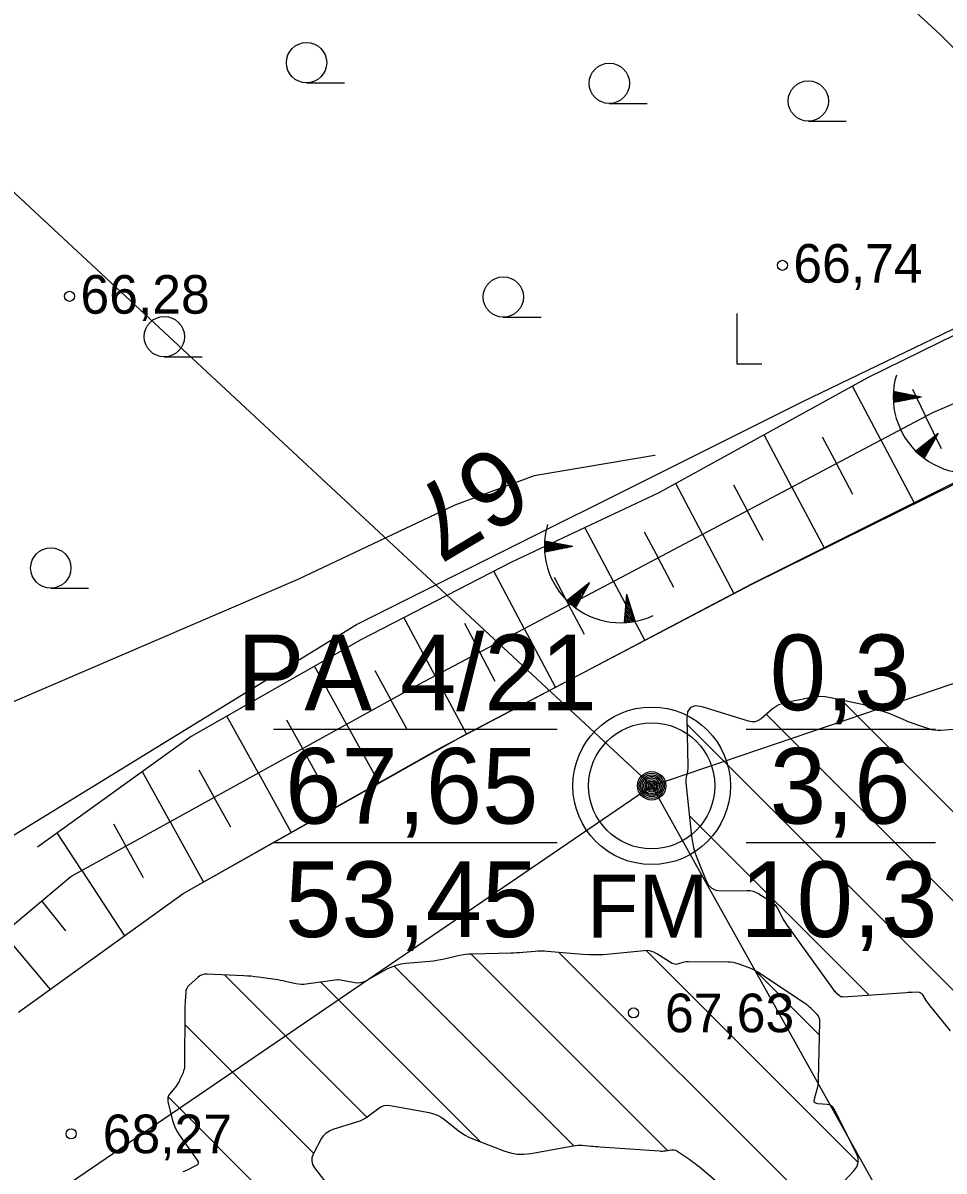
# Model space of a CAD drawing. Extents: x 532503 to 539665, y 6557663 to 6561526.
# Drawn here: x 535265.8 to 535324.2, y 6559863.4 to 6559936.3 of the extents above; entities that cross this region are included whole.
import ezdxf

# ---------------------------------------------------------------- set-up
doc = ezdxf.new("R2010")
doc.units = 0
for name, color, linetype in [('Default', 7, 'Continuous'), ('GEOLPUNKT', 7, 'Continuous'), ('HALJASTUS', 7, 'Continuous'), ('HORISONTAAL-EH2000', 7, 'Continuous'), ('Kaevandatud ala', 7, 'Continuous'), ('KORGUS-EH2000', 7, 'Continuous'), ('Lamami horisontaal_EH2000', 7, 'Continuous'), ('Lõige', 7, 'Continuous'), ('Proovid', 7, 'Continuous'), ('RELJEEF', 7, 'Continuous')]:
    doc.layers.add(name, color=color, linetype=linetype)

# ---------------------------------------------------------------- blocks, each defined once
blk = doc.blocks.new('RAIESM')
at = {"layer": 'Default'}
for points in [[(0, 2), (0, 0)], [(0, 0), (1, 0)]]:
    blk.add_lwpolyline(points, dxfattribs=at)
blk = doc.blocks.new('HARVIK')
at = {"layer": 'HALJASTUS'}
blk.add_line((0, -0.8), (1.5, -0.8), dxfattribs=at)
blk.add_circle((0, 0), 0.8, dxfattribs=at)

msp = doc.modelspace()

# ---------------------------------------------------------------- linework, layer by layer
at = {"layer": 'GEOLPUNKT'}
for p, q in [((535281.655, 6559891.451), (535299.655, 6559891.451)), ((535311.655, 6559891.451), (535323.655, 6559891.451)), ((535281.655, 6559884.251), (535299.655, 6559884.251)), ((535311.655, 6559884.251), (535323.655, 6559884.251))]:
    msp.add_line(p, q, dxfattribs=at)
for radius in [5, 4, 0.9, 0.801, 0.7, 0.6, 0.5, 0.4, 0.3, 0.2, 0.1]:
    msp.add_circle((535305.655, 6559887.851), radius, dxfattribs=at)
at = {"layer": 'HORISONTAAL-EH2000'}
msp.add_lwpolyline([(535305.885, 6559908.809), (535305.842, 6559908.814), (535298.198, 6559907.517), (535293.16, 6559905.657), (535283.197, 6559900.951), (535256.192, 6559889.327), (535239.185, 6559882.188), (535229.031, 6559879.316), (535223.831, 6559878.54), (535205.549, 6559877.823), (535200.022, 6559876.846), (535189.2, 6559873.548), (535161, 6559862.943), (535143.069, 6559857.274), (535133.961, 6559854.956), (535125.581, 6559853.165), (535108.623, 6559850.369), (535095.453, 6559849.117), (535088.898, 6559849.291), (535083.275, 6559850.063), (535072.085, 6559852.426), (535042.226, 6559857.773)], dxfattribs=at)
at = {"layer": 'Kaevandatud ala'}
for p, q in [((535317.672, 6559893.299), (535344.443, 6559866.528)), ((535312.923, 6559892.392), (535341.11, 6559864.204)), ((535307.887, 6559891.77), (535333.788, 6559865.87)), ((535308.045, 6559885.956), (535319.423, 6559874.578)), ((535294.203, 6559877.17), (535306.663, 6559864.711)), ((535299.755, 6559877.275), (535315.17, 6559861.861)), ((535305.297, 6559877.39), (535318.754, 6559863.933)), ((535289.313, 6559876.404), (535300.702, 6559865.014)), ((535312.237, 6559876.107), (535316.31, 6559872.034)), ((535278.552, 6559875.851), (535287.579, 6559866.824)), ((535284.667, 6559875.393), (535294.816, 6559865.244)), ((535276.035, 6559872.711), (535284.227, 6559864.519)), ((535274.978, 6559868.111), (535299.734, 6559843.355))]:
    msp.add_line(p, q, dxfattribs=at)
for points in [[(535325.558, 6559891.481), (535323.992, 6559891.37), (535323.797, 6559891.366), (535323.605, 6559891.38), (535323.415, 6559891.414), (535323.228, 6559891.466), (535322.483, 6559891.714), (535322.297, 6559891.778), (535322.113, 6559891.846), (535321.931, 6559891.918), (535321.75, 6559891.994), (535321.015, 6559892.312), (535320.832, 6559892.389), (535320.648, 6559892.462), (535320.462, 6559892.532), (535320.274, 6559892.598), (535319.495, 6559892.865), (535319.301, 6559892.928), (535319.106, 6559892.985), (535318.91, 6559893.036), (535318.711, 6559893.081), (535316.993, 6559893.442), (535316.659, 6559893.494), (535316.326, 6559893.511), (535315.992, 6559893.494), (535315.659, 6559893.44), (535314.113, 6559893.113), (535313.891, 6559893.052), (535313.682, 6559892.965), (535313.486, 6559892.853), (535313.302, 6559892.715), (535312.593, 6559892.112), (535312.41, 6559891.989), (535312.216, 6559891.92), (535312.01, 6559891.907), (535311.793, 6559891.948), (535308.867, 6559892.857), (535308.425, 6559892.928), (535308.113, 6559892.828), (535307.931, 6559892.555), (535307.879, 6559892.11), (535307.953, 6559889.102), (535307.953, 6559889.013), (535307.947, 6559888.926), (535307.935, 6559888.839), (535307.918, 6559888.752), (535307.838, 6559888.407), (535307.822, 6559888.321), (535307.813, 6559888.234), (535307.812, 6559888.146), (535307.818, 6559888.058), (535308.187, 6559884.647), (535308.238, 6559884.285), (535308.314, 6559883.928), (535308.415, 6559883.577), (535308.54, 6559883.233), (535309.106, 6559881.821), (535309.26, 6559881.543), (535309.469, 6559881.345), (535309.731, 6559881.228), (535310.048, 6559881.191), (535311.69, 6559881.209), (535311.894, 6559881.197), (535312.09, 6559881.156), (535312.278, 6559881.087), (535312.458, 6559880.989), (535313.257, 6559880.478), (535313.377, 6559880.389), (535313.483, 6559880.288), (535313.575, 6559880.174), (535313.651, 6559880.046), (535313.93, 6559879.509), (535314.002, 6559879.376), (535314.079, 6559879.246), (535314.16, 6559879.118), (535314.246, 6559878.994), (535317.121, 6559874.979), (535317.166, 6559874.92), (535317.214, 6559874.863), (535317.265, 6559874.809), (535317.319, 6559874.758), (535317.541, 6559874.558), (535317.599, 6559874.515), (535317.662, 6559874.485), (535317.729, 6559874.47), (535317.801, 6559874.468), (535321.818, 6559874.742), (535321.907, 6559874.747), (535321.997, 6559874.752), (535322.086, 6559874.755), (535322.176, 6559874.758), (535322.533, 6559874.766), (535322.617, 6559874.758), (535322.691, 6559874.731), (535322.754, 6559874.684), (535322.806, 6559874.618), (535323.049, 6559874.226), (535323.106, 6559874.136), (535323.167, 6559874.048), (535323.23, 6559873.962), (535323.296, 6559873.879), (535324.585, 6559872.29)], [(535317.557, 6559862.427), (535318.486, 6559863.42), (535318.67, 6559863.675), (535318.758, 6559863.944), (535318.749, 6559864.227), (535318.644, 6559864.524), (535317.226, 6559867.336), (535317.148, 6559867.455), (535317.05, 6559867.543), (535316.931, 6559867.6), (535316.791, 6559867.627), (535316.192, 6559867.672), (535316.066, 6559867.7), (535315.988, 6559867.761), (535315.957, 6559867.856), (535315.974, 6559867.984), (535316.148, 6559868.599), (535316.186, 6559868.751), (535316.214, 6559868.904), (535316.232, 6559869.058), (535316.241, 6559869.214), (535316.331, 6559872.879), (535316.322, 6559873.008), (535316.288, 6559873.127), (535316.231, 6559873.236), (535316.148, 6559873.336), (535315.77, 6559873.714), (535315.673, 6559873.806), (535315.572, 6559873.893), (535315.467, 6559873.975), (535315.358, 6559874.051), (535312.389, 6559876.014), (535312.245, 6559876.103), (535312.097, 6559876.183), (535311.944, 6559876.253), (535311.786, 6559876.315), (535311.146, 6559876.542), (535310.985, 6559876.592), (535310.821, 6559876.628), (535310.655, 6559876.651), (535310.486, 6559876.659), (535307.994, 6559876.688), (535307.903, 6559876.685), (535307.813, 6559876.676), (535307.725, 6559876.661), (535307.637, 6559876.639), (535307.287, 6559876.537), (535307.2, 6559876.52), (535307.117, 6559876.523), (535307.036, 6559876.544), (535306.957, 6559876.583), (535305.989, 6559877.196), (535305.797, 6559877.296), (535305.598, 6559877.362), (535305.39, 6559877.392), (535305.174, 6559877.387), (535303.015, 6559877.164), (535302.582, 6559877.13), (535302.148, 6559877.115), (535301.715, 6559877.121), (535301.281, 6559877.147), (535299.025, 6559877.336), (535298.833, 6559877.348), (535298.641, 6559877.352), (535298.448, 6559877.348), (535298.256, 6559877.336), (535297.487, 6559877.271), (535297.295, 6559877.256), (535297.102, 6559877.244), (535296.909, 6559877.236), (535296.717, 6559877.23), (535294.295, 6559877.175), (535294.065, 6559877.164), (535293.837, 6559877.141), (535293.61, 6559877.107), (535293.385, 6559877.061), (535292.486, 6559876.853), (535292.261, 6559876.805), (535292.035, 6559876.765), (535291.807, 6559876.732), (535291.578, 6559876.708), (535290.054, 6559876.569), (535289.742, 6559876.525), (535289.439, 6559876.45), (535289.146, 6559876.343), (535288.863, 6559876.206), (535287.504, 6559875.461), (535287.345, 6559875.389), (535287.181, 6559875.347), (535287.012, 6559875.334), (535286.838, 6559875.35), (535285.792, 6559875.534), (535285.78, 6559875.536), (535285.768, 6559875.539), (535285.745, 6559875.546), (535285.739, 6559875.547), (535285.733, 6559875.548), (535285.727, 6559875.548), (535285.721, 6559875.547), (535283.746, 6559875.258), (535283.58, 6559875.242), (535283.415, 6559875.241), (535283.251, 6559875.255), (535283.087, 6559875.285), (535282.433, 6559875.437), (535282.269, 6559875.473), (535282.105, 6559875.505), (535281.939, 6559875.534), (535281.773, 6559875.559), (535280.711, 6559875.706), (535280.478, 6559875.735), (535280.245, 6559875.76), (535280.011, 6559875.779), (535279.777, 6559875.793), (535277.457, 6559875.903), (535277.294, 6559875.896), (535277.141, 6559875.859), (535276.998, 6559875.792), (535276.867, 6559875.694), (535276.318, 6559875.205), (535276.226, 6559875.106), (535276.157, 6559874.996), (535276.113, 6559874.873), (535276.092, 6559874.739), (535276.059, 6559874.181), (535276.051, 6559874.041), (535276.046, 6559873.901), (535276.042, 6559873.761), (535276.04, 6559873.621), (535276.019, 6559870.104), (535276.013, 6559869.985), (535275.995, 6559869.869), (535275.964, 6559869.755), (535275.923, 6559869.643), (535275.732, 6559869.201), (535275.681, 6559869.093), (535275.622, 6559868.989), (535275.556, 6559868.89), (535275.484, 6559868.795), (535275.084, 6559868.31), (535275.008, 6559868.194), (535274.964, 6559868.072), (535274.951, 6559867.942), (535274.97, 6559867.805), (535275.266, 6559866.609), (535275.338, 6559866.367), (535275.431, 6559866.136), (535275.545, 6559865.914), (535275.681, 6559865.703), (535276.823, 6559864.093), (535276.882, 6559863.978), (535276.885, 6559863.878), (535276.834, 6559863.792), (535276.726, 6559863.721), (535276.186, 6559863.464), (535276.049, 6559863.403), (535275.911, 6559863.349)], [(535285.137, 6559862.505), (535284.291, 6559863.598), (535284.164, 6559863.811), (535284.109, 6559864.03), (535284.124, 6559864.255), (535284.21, 6559864.486), (535284.697, 6559865.426), (535284.835, 6559865.641), (535285.005, 6559865.818), (535285.209, 6559865.955), (535285.445, 6559866.053), (535286.96, 6559866.523), (535287.153, 6559866.592), (535287.337, 6559866.677), (535287.514, 6559866.778), (535287.682, 6559866.895), (535288.337, 6559867.395), (535288.506, 6559867.499), (535288.684, 6559867.563), (535288.872, 6559867.586), (535289.07, 6559867.569), (535291.546, 6559867.106), (535291.808, 6559867.041)], [(535291.808, 6559867.041), (535292.057, 6559866.945), (535292.292, 6559866.819), (535292.513, 6559866.663), (535293.37, 6559865.978), (535293.589, 6559865.816), (535293.819, 6559865.672), (535294.059, 6559865.546), (535294.31, 6559865.439), (535296.284, 6559864.679), (535296.701, 6559864.55), (535297.123, 6559864.48), (535297.551, 6559864.47), (535297.985, 6559864.52), (535300.679, 6559865.011), (535300.819, 6559865.032), (535300.96, 6559865.043), (535301.101, 6559865.045), (535301.243, 6559865.038), (535301.811, 6559864.99), (535301.953, 6559864.978), (535302.095, 6559864.967), (535302.237, 6559864.956), (535302.379, 6559864.946), (535306.147, 6559864.673), (535306.242, 6559864.669), (535306.337, 6559864.67), (535306.431, 6559864.677), (535306.526, 6559864.689), (535306.903, 6559864.749), (535306.995, 6559864.755), (535307.084, 6559864.745), (535307.169, 6559864.717), (535307.25, 6559864.673), (535308.07, 6559864.128), (535308.232, 6559864.017), (535308.39, 6559863.902), (535308.544, 6559863.782), (535308.696, 6559863.658), (535311.398, 6559861.369)]]:
    msp.add_lwpolyline(points, dxfattribs=at)
at = {"layer": 'KORGUS-EH2000'}
for centre in [(535313.948, 6559920.888), (535268.723, 6559918.92), (535304.499, 6559873.436), (535268.832, 6559865.759)]:
    msp.add_circle(centre, 0.32, dxfattribs=at)
at = {"layer": 'Lamami horisontaal_EH2000'}
msp.add_lwpolyline([(535263.595, 6559978.897), (535279.24, 6559969.378), (535289.33, 6559963.743), (535300.974, 6559955.07), (535311.39, 6559947.134), (535323.977, 6559935.519), (535330.762, 6559928.747), (535346.894, 6559909.063), (535357.898, 6559891.444), (535363.729, 6559880.874), (535369.418, 6559869.423), (535381.896, 6559830.286), (535384.697, 6559817.512), (535386.218, 6559804.738), (535387.08, 6559785.663), (535387.408, 6559764.957), (535386.422, 6559734.519), (535381.944, 6559720.776), (535381.85, 6559720.569), (535371.908, 6559697.985), (535369.403, 6559694.108), (535347.091, 6559670.221), (535323.306, 6559653.308), (535295.148, 6559638.437)], dxfattribs=at)
at = {"layer": 'Lõige'}
for points in [[(535150.705, 6560087.504), (535159.93, 6560069.75), (535218.82, 6559968.7), (535305.655, 6559887.851), (535461.67, 6559608.38), (535506.03, 6559511.29), (535514.367, 6559493.043)], [(533917.426, 6559650.435), (533949.04, 6559659.85), (534215.74, 6559786.31), (534470.46, 6559695.5), (534707.91, 6559763.06), (534929.16, 6559826.01), (535198.18, 6559814.49), (535305.655, 6559887.851), (535520.8, 6559960.87), (535543.919, 6559970.997)]]:
    msp.add_lwpolyline(points, dxfattribs=at)
at = {"layer": 'RELJEEF'}
for p, q in [((535320.198, 6559909.808), (535318.389, 6559913.224)), ((535320.977, 6559912.555), (535321.295, 6559912.81)), ((535320.977, 6559912.453), (535321.398, 6559912.79)), ((535320.978, 6559912.659), (535321.192, 6559912.83)), ((535320.98, 6559912.353), (535321.501, 6559912.77)), ((535320.982, 6559912.765), (535321.089, 6559912.85)), ((535320.985, 6559912.254), (535321.604, 6559912.75)), ((535322.769, 6559912.525), (535320.988, 6559912.869)), ((535321.023, 6559912.182), (535321.708, 6559912.73)), ((535321.193, 6559912.216), (535321.811, 6559912.71)), ((535321.362, 6559912.249), (535321.914, 6559912.69)), ((535321.532, 6559912.282), (535322.017, 6559912.671)), ((535321.701, 6559912.316), (535322.12, 6559912.651)), ((535321.871, 6559912.349), (535322.223, 6559912.631)), ((535322.041, 6559912.382), (535322.326, 6559912.611)), ((535322.191, 6559913.022), (535323.026, 6559911.305)), ((535322.21, 6559912.415), (535322.429, 6559912.591)), ((535322.38, 6559912.449), (535322.533, 6559912.571)), ((535322.55, 6559912.482), (535322.636, 6559912.551)), ((535322.769, 6559912.525), (535320.99, 6559912.176)), ((535324.031, 6559909.24), (535323.026, 6559911.305)), ((535314.542, 6559906.814), (535312.784, 6559910.134)), ((535316.478, 6559909.995), (535317.37, 6559908.311)), ((535320.198, 6559909.808), (535322.313, 6559905.813)), ((535323.832, 6559910.221), (535322.41, 6559909.094)), ((535323.832, 6559910.221), (535322.936, 6559908.643)), ((535323.124, 6559908.973), (535323.148, 6559909.679)), ((535323.209, 6559909.124), (535323.231, 6559909.745)), ((535323.294, 6559909.274), (535323.313, 6559909.81)), ((535323.38, 6559909.424), (535323.396, 6559909.875)), ((535323.465, 6559909.575), (535323.478, 6559909.94)), ((535323.55, 6559909.725), (535323.56, 6559910.006)), ((535323.636, 6559909.875), (535323.643, 6559910.071)), ((535323.721, 6559910.026), (535323.725, 6559910.136)), ((535322.485, 6559909.021), (535322.49, 6559909.158)), ((535322.562, 6559908.95), (535322.572, 6559909.223)), ((535322.64, 6559908.881), (535322.654, 6559909.288)), ((535322.718, 6559908.815), (535322.737, 6559909.353)), ((535322.796, 6559908.751), (535322.819, 6559909.419)), ((535322.874, 6559908.691), (535322.901, 6559909.484)), ((535322.953, 6559908.673), (535322.984, 6559909.549)), ((535323.038, 6559908.823), (535323.066, 6559909.614)), ((535318.41, 6559906.346), (535317.37, 6559908.311)), ((535308.885, 6559903.819), (535307.178, 6559907.045)), ((535310.847, 6559906.953), (535311.713, 6559905.317)), ((535314.542, 6559906.814), (535316.588, 6559902.949)), ((535312.719, 6559903.417), (535311.713, 6559905.317)), ((535303.229, 6559900.825), (535301.419, 6559904.244)), ((535305.187, 6559903.966), (535306.057, 6559902.322)), ((535308.885, 6559903.819), (535310.875, 6559900.061)), ((535298.853, 6559903.069), (535299.171, 6559903.324)), ((535298.853, 6559902.967), (535299.274, 6559903.304)), ((535298.854, 6559903.173), (535299.068, 6559903.344)), ((535298.856, 6559902.867), (535299.377, 6559903.284)), ((535298.858, 6559903.278), (535298.965, 6559903.364)), ((535298.861, 6559902.768), (535299.48, 6559903.264)), ((535300.645, 6559903.039), (535298.864, 6559903.383)), ((535298.899, 6559902.696), (535299.584, 6559903.244)), ((535299.069, 6559902.729), (535299.687, 6559903.224)), ((535299.238, 6559902.763), (535299.79, 6559903.204)), ((535299.408, 6559902.796), (535299.893, 6559903.184)), ((535299.577, 6559902.829), (535299.996, 6559903.164)), ((535299.747, 6559902.863), (535300.099, 6559903.144)), ((535299.917, 6559902.896), (535300.202, 6559903.125)), ((535300.086, 6559902.929), (535300.305, 6559903.105)), ((535300.256, 6559902.962), (535300.409, 6559903.085)), ((535300.426, 6559902.996), (535300.512, 6559903.065)), ((535300.645, 6559903.039), (535298.866, 6559902.69)), ((535307.05, 6559900.447), (535306.057, 6559902.322)), ((535297.573, 6559897.831), (535295.645, 6559901.471)), ((535299.461, 6559901.103), (535300.401, 6559899.328)), ((535301.708, 6559900.734), (535300.286, 6559899.608)), ((535301.708, 6559900.734), (535300.812, 6559899.157)), ((535301, 6559899.487), (535301.025, 6559900.193)), ((535301.085, 6559899.637), (535301.107, 6559900.258)), ((535301.17, 6559899.788), (535301.189, 6559900.324)), ((535301.256, 6559899.938), (535301.272, 6559900.389)), ((535301.341, 6559900.088), (535301.354, 6559900.454)), ((535301.426, 6559900.239), (535301.436, 6559900.519)), ((535301.512, 6559900.389), (535301.519, 6559900.585)), ((535301.597, 6559900.539), (535301.601, 6559900.65)), ((535303.229, 6559900.825), (535305.211, 6559897.082)), ((535300.361, 6559899.535), (535300.366, 6559899.671)), ((535300.439, 6559899.463), (535300.448, 6559899.737)), ((535300.516, 6559899.395), (535300.53, 6559899.802)), ((535300.594, 6559899.329), (535300.613, 6559899.867)), ((535300.672, 6559899.265), (535300.695, 6559899.932)), ((535300.75, 6559899.204), (535300.777, 6559899.998)), ((535300.829, 6559899.186), (535300.86, 6559900.063)), ((535300.914, 6559899.337), (535300.942, 6559900.128)), ((535304.051, 6559900.017), (535303.915, 6559898.209)), ((535304.33, 6559899.146), (535304.009, 6559899.463)), ((535304.277, 6559899.31), (535304.017, 6559899.567)), ((535304.225, 6559899.475), (535304.025, 6559899.672)), ((535304.172, 6559899.639), (535304.033, 6559899.777)), ((535304.119, 6559899.804), (535304.041, 6559899.882)), ((535304.051, 6559900.017), (535304.604, 6559898.29)), ((535301.39, 6559897.46), (535300.401, 6559899.328)), ((535304.429, 6559898.26), (535303.954, 6559898.729)), ((535304.526, 6559898.276), (535303.962, 6559898.834)), ((535304.593, 6559898.322), (535303.97, 6559898.939)), ((535304.541, 6559898.487), (535303.978, 6559899.044)), ((535304.488, 6559898.652), (535303.986, 6559899.148)), ((535304.435, 6559898.816), (535303.994, 6559899.253)), ((535304.383, 6559898.981), (535304.001, 6559899.358)), ((535291.916, 6559894.836), (535289.936, 6559898.526)), ((535293.773, 6559898.169), (535294.744, 6559896.334)), ((535304.02, 6559898.215), (535303.923, 6559898.31)), ((535304.125, 6559898.223), (535303.931, 6559898.415)), ((535304.228, 6559898.233), (535303.939, 6559898.52)), ((535304.33, 6559898.246), (535303.946, 6559898.625)), ((535297.573, 6559897.831), (535299.547, 6559894.102)), ((535295.73, 6559894.473), (535294.744, 6559896.334)), ((535286.305, 6559891.759), (535284.27, 6559895.442)), ((535288.083, 6559895.171), (535289.106, 6559893.307)), ((535291.916, 6559894.836), (535293.904, 6559891.133)), ((535290.116, 6559891.465), (535289.106, 6559893.307)), ((535280.703, 6559888.664), (535278.711, 6559892.27)), ((535282.497, 6559892.034), (535283.504, 6559890.212)), ((535286.305, 6559891.759), (535288.353, 6559888.052)), ((535284.536, 6559888.343), (535283.504, 6559890.212)), ((535275.101, 6559885.569), (535273.344, 6559888.749)), ((535276.932, 6559888.873), (535277.902, 6559887.117)), ((535280.703, 6559888.664), (535282.784, 6559884.898)), ((535278.951, 6559885.219), (535277.902, 6559887.117)), ((535269.499, 6559882.474), (535267.941, 6559884.866)), ((535271.514, 6559885.445), (535272.3, 6559884.022)), ((535275.101, 6559885.569), (535277.215, 6559881.743)), ((535273.411, 6559882.01), (535272.3, 6559884.022)), ((535269.499, 6559882.474), (535272.203, 6559878.324)), ((535268.481, 6559878.64), (535266.96, 6559880.545)), ((535264.509, 6559878.488), (535267.496, 6559874.926))]:
    msp.add_line(p, q, dxfattribs=at)
for points in [[(535265.494, 6559873.481), (535275.933, 6559881.017), (535292.336, 6559890.308), (535312.018, 6559900.663), (535333.248, 6559911.284), (535367.64, 6559927.766), (535387.933, 6559937.741), (535409.502, 6559946.68), (535425.323, 6559952.185), (535428.239, 6559953.667), (535428.746, 6559956.906), (535429.149, 6559961.063), (535429.829, 6559961.816), (535429.058, 6559963.653), (535425.784, 6559967.622), (535422.069, 6559971.31), (535417.005, 6559978.456), (535412.969, 6559983.282), (535408.421, 6559986.166), (535398.888, 6559989.282)], [(535244.607, 6559868.299), (535261.949, 6559882.758), (535286.92, 6559898.096), (535315.197, 6559912.222), (535344.983, 6559926.588), (535386.159, 6559945.183), (535409.54, 6559956.432), (535421.277, 6559959.881), (535426.87, 6559964.94)], [(535250.552, 6559865.316), (535261.365, 6559875.852), (535268.802, 6559882.089), (535290.903, 6559894.3), (535323.494, 6559911.553), (535347.08, 6559921.682), (535377.332, 6559936.91), (535406.032, 6559949.274), (535425.297, 6559956.673), (535426.746, 6559961.414)], [(535250.552, 6559865.316), (535261.365, 6559875.852), (535268.802, 6559882.089), (535290.903, 6559894.3), (535323.494, 6559911.553), (535347.08, 6559921.682), (535377.332, 6559936.91), (535406.032, 6559949.274), (535425.297, 6559956.673), (535426.746, 6559961.414)], [(535426.746, 6559961.414), (535416.222, 6559958.013), (535405.403, 6559954.715), (535396.236, 6559949.694), (535381.283, 6559943.149), (535363.148, 6559934.092), (535348.485, 6559927.086), (535330.46, 6559919.198), (535319.383, 6559913.772), (535306.108, 6559906.455), (535296.753, 6559902.043), (535287.202, 6559897.116), (535276.443, 6559890.976), (535266.684, 6559883.962)], [(535265.494, 6559873.481), (535275.933, 6559881.017), (535293.72, 6559891.036), (535312.051, 6559900.68), (535341.577, 6559915.275), (535343.558, 6559916.225), (535344.767, 6559916.804), (535346.849, 6559917.802), (535349.569, 6559919.106), (535353.834, 6559921.15), (535354.405, 6559921.423), (535358.502, 6559923.387), (535359.678, 6559923.95), (535359.846, 6559924.031), (535365.689, 6559926.831), (535370.615, 6559929.228)]]:
    msp.add_lwpolyline(points, dxfattribs=at)
for centre in [(535325.82, 6559912.533), (535303.696, 6559903.047)]:
    msp.add_arc(centre, 4.844, 163.42341, 295.17451, dxfattribs=at)

# ---------------------------------------------------------------- block references
at = {"layer": 'HALJASTUS', "xscale": 1.6, "yscale": 1.6000000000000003}
for name, p in [('HARVIK', (535283.76, 6559933.749)), ('HARVIK', (535302.965, 6559932.439)), ('HARVIK', (535315.593, 6559931.315)), ('HARVIK', (535296.241, 6559918.88)), ('HARVIK', (535274.735, 6559916.359)), ('RAIESM', (535311.052, 6559914.636)), ('HARVIK', (535267.537, 6559901.674))]:
    msp.add_blockref(name, p, dxfattribs=at)

# ---------------------------------------------------------------- texts
at = {"layer": 'GEOLPUNKT'}
for s, p in [('PA 4/21', (535279.343, 6559892.651)), ('0,3', (535313.148, 6559892.651)), ('67,65', (535282.402, 6559885.451)), ('3,6', (535313.148, 6559885.451)), ('53,45', (535282.402, 6559878.251)), ('10,3', (535311.284, 6559878.251))]:
    msp.add_text(s, height=4.8, dxfattribs=at).set_placement(p)
at = {"layer": 'HORISONTAAL-EH2000'}
msp.add_text('67', height=4.8, rotation=211.03059, dxfattribs=at).set_placement((535295.92, 6559909.699))
at = {"layer": 'KORGUS-EH2000'}
for s, p in [('66,74', (535314.643, 6559919.787)), ('66,28', (535269.418, 6559917.818)), ('67,63 ', (535306.499, 6559872.211)), ('68,27 ', (535270.832, 6559864.534))]:
    msp.add_text(s, height=2.45, dxfattribs=at).set_placement(p)
at = {"layer": 'Proovid'}
msp.add_text('FM', height=4, dxfattribs=at).set_placement((535301.537, 6559878.212))

doc.saveas('drawing.dxf')
